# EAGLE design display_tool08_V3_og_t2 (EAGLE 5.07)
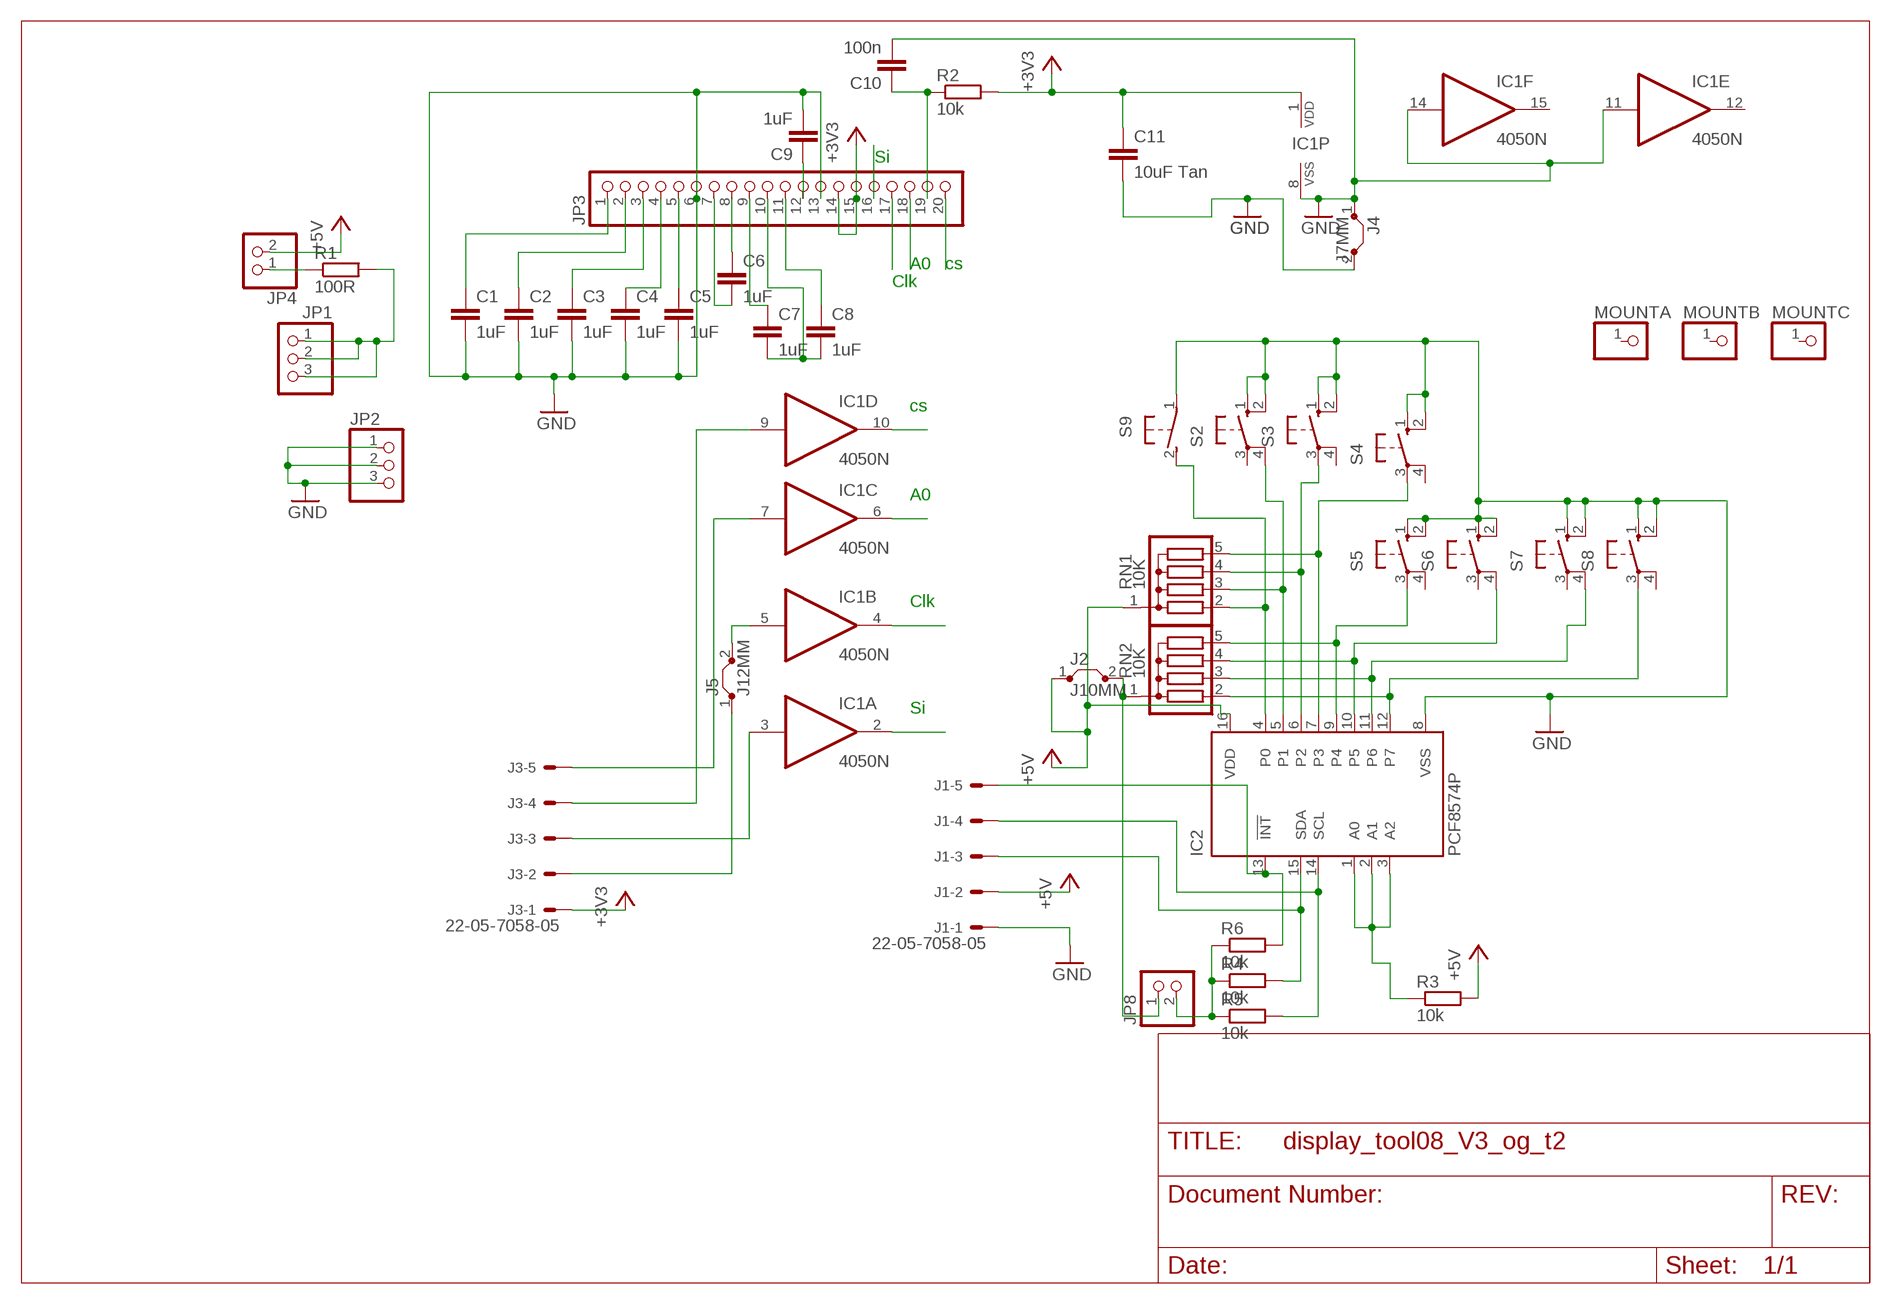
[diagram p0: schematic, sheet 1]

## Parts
C1  1uF  C-EU025-025X050  [C025-025X050]
C2  1uF  C-EU025-025X050  [C025-025X050]
C3  1uF  C-EU025-025X050  [C025-025X050]
C4  1uF  C-EU025-025X050  [C025-025X050]
C5  1uF  C-EU025-025X050  [C025-025X050]
C6  1uF  C-EU025-025X050  [C025-025X050]
C7  1uF  C-EU025-025X050  [C025-025X050]
C8  1uF  C-EU025-025X050  [C025-025X050]
C9  1uF  C-EU025-025X050  [C025-025X050]
C10  100n  C-EU025-025X050  [C025-025X050]
C11  10uF Tan  C-EU025-025X050  [C025-025X050]
IC1  4050N  [DIL16]
IC2  PCF8574P  [DIL16]
J1  22-05-7058-05  [7395-05]
J2  J10MM  [10]
J3  22-05-7058-05  [7395-05]
J4  J7MM  [07]
J5  J12MM  [12]
JP1  PINHD-1X3  [1X03]
JP2  PINHD-1X3  [1X03]
JP3  PINHD-1X20  [1X20]
JP4  PINHD-1X2  [1X02]
JP8  PINHD-1X2  [1X02]
MOUNTA  PINHD-1X1  [1X01]
MOUNTB  PINHD-1X1  [1X01]
MOUNTC  PINHD-1X1  [1X01]
R1  100R  R-EU_0309/12  [0309/12]
R2  10k  R-EU_0309/12  [0309/12]
R3  10k  R-EU_0207/7  [0207/7]
R4  10k  R-EU_0207/7  [0207/7]
R5  10k  R-EU_0207/7  [0207/7]
R6  10k  R-EU_0207/7  [0207/7]
RN1  10K  G04R  [SIL5]
RN2  10K  G04R  [SIL5]
S2  10-XX  [B3F-10XX]
S3  10-XX  [B3F-10XX]
S4  10-XX  [B3F-10XX]
S5  10-XX  [B3F-10XX]
S6  10-XX  [B3F-10XX]
S7  10-XX  [B3F-10XX]
S8  10-XX  [B3F-10XX]
S9  31-XX  [B3F-31XX]

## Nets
+3V3 [big]: C11.1 IC1.1(P:VDD) J3.1 JP3.14 JP3.15 R2.2
+5V [big]: IC2.16(VDD) J1.2 J2.1 JP4.2 R3.2 RN1.1
A0 [big]: IC1.6(C:O) JP3.18
CLK: IC1.4(B:O) JP3.17
CS: IC1.10(D:O) JP3.20
GND: C1.2 C2.2 C3.2 C4.2 C5.2 C9.2 C10.2 C11.2 IC1.8(P:VSS) IC1.11(E:I) IC1.14(F:I) IC2.8(VSS) J1.1 J4.1 J4.2 JP2.1 JP2.2 JP2.3 JP3.6 JP3.13 S2.1(S) S2.2(S1) S3.1(S) S3.2(S1) S4.1(S) S4.2(S1) S5.1(S) S5.2(S1) S6.1(S) S6.2(S1) S7.1(S) S7.2(S1) S8.1(S) S8.2(S1) S9.1(P)
N$1 [big]: JP4.1 R1.1
N$2 [big]: JP1.1 JP1.2 JP1.3 R1.2
N$3 [big]: IC2.7(P3) RN1.5 S4.3(P)
N$4 [big]: IC2.12(P7) RN2.2 S8.3(P)
N$5 [big]: C1.1 JP3.1
N$6 [big]: C2.1 JP3.2
N$7 [big]: C3.1 JP3.3
N$8 [big]: C4.1 JP3.4
N$9 [big]: C5.1 JP3.5
N$10 [big]: IC2.6(P2) RN1.4 S3.3(P)
N$11 [big]: IC2.11(P6) RN2.3 S7.4(P1)
N$12 [big]: C6.2 JP3.7
N$13 [big]: C6.1 JP3.8
N$14 [big]: C7.2 C8.2 JP3.10
N$15 [big]: IC2.5(P1) RN1.3 S2.4(P1)
N$16 [big]: C7.1 JP3.9
N$17 [big]: C8.1 JP3.11
N$18 [big]: C9.1 JP3.12
N$19 [big]: C10.1 JP3.19 R2.1
N$20 [big]: IC2.10(P5) RN2.4 S6.4(P1)
N$21 [big]: IC2.4(P0) RN1.2 S9.2(S)
N$22 [big]: IC2.9(P4) RN2.5 S5.3(P)
N$25 [mid]: IC1.3(A:I) J3.3
N$26 [big]: J3.2 J5.1
N$27 [mid]: IC1.7(C:I) J3.5
N$28: IC1.9(D:I) J3.4
N$29 [big]: IC1.5(B:I) J5.2
N$30 [big]: IC2.13(!INT) J1.5 R6.2
N$31: IC2.1(A0) IC2.2(A1) IC2.3(A2) R3.1
N$34 [big]: J2.2 JP8.1 RN2.1
N$35 [big]: JP8.2 R4.1 R5.1 R6.1
SCL [big]: IC2.14(SCL) J1.4 R5.2
SDA [big]: IC2.15(SDA) J1.3 R4.2
SI: IC1.2(A:O) JP3.16
Unconnected: IC1.12(E:O) IC1.15(F:O) MOUNTA.1 MOUNTB.1 MOUNTC.1 S2.3(P) S3.4(P1) S4.4(P1) S5.4(P1) S6.3(P) S7.3(P) S8.4(P1)

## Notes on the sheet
- Si
- A0 | cs
- Clk
- cs
- A0
- Clk
- Si

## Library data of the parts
C1-C11 = rcl:C-EU: CAPACITOR, European symbol
IC1 = 40xx:4050: Hex non-inverting BUFFER
IC2 = micro-philips:PCF8574: I2C-Bus Remote 8-bit I/O expander http://www.semiconductors.philips.com/acrobat_download/datasheets/PCF8574_4.pdf
J1 J3 = con-molex:22-?-05: CONNECTOR wire to board 2.54 mm (.1 inch) pitch header
J2 J4 J5 = jumper:J: Bridge
JP1 JP2 = pinhead:PINHD-1X3: PIN HEADER
JP3 = pinhead:PINHD-1X20: PIN HEADER
JP4 JP8 = pinhead:PINHD-1X2: PIN HEADER
MOUNTA MOUNTB MOUNTC = pinhead:PINHD-1X1: PIN HEADER
R1-R6 = rcl:R-EU_: RESISTOR, European symbol
RN1 RN2 = resistor-sil:G04R: SIL RESISTOR
S2-S8 = switch-omron:10-XX: OMRON SWITCH
S9 = switch-omron:31-XX: OMRON SWITCH

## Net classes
0 default: width 1.016 mm, drill 1.016 mm, clearance 0.762 mm
1 signal: width 0.813 mm, drill 1.016 mm, clearance 0.762 mm to class 0, clearance 0.762 mm
2 big: width 1.27 mm, clearance 0.762 mm to class 0, clearance 0.762 mm to class 1, clearance 0.762 mm
3 mid: width 1.016 mm, drill 1.016 mm, clearance 0.508 mm to class 0, clearance 0.508 mm to class 1, clearance 0.508 mm to class 2, clearance 0.508 mm

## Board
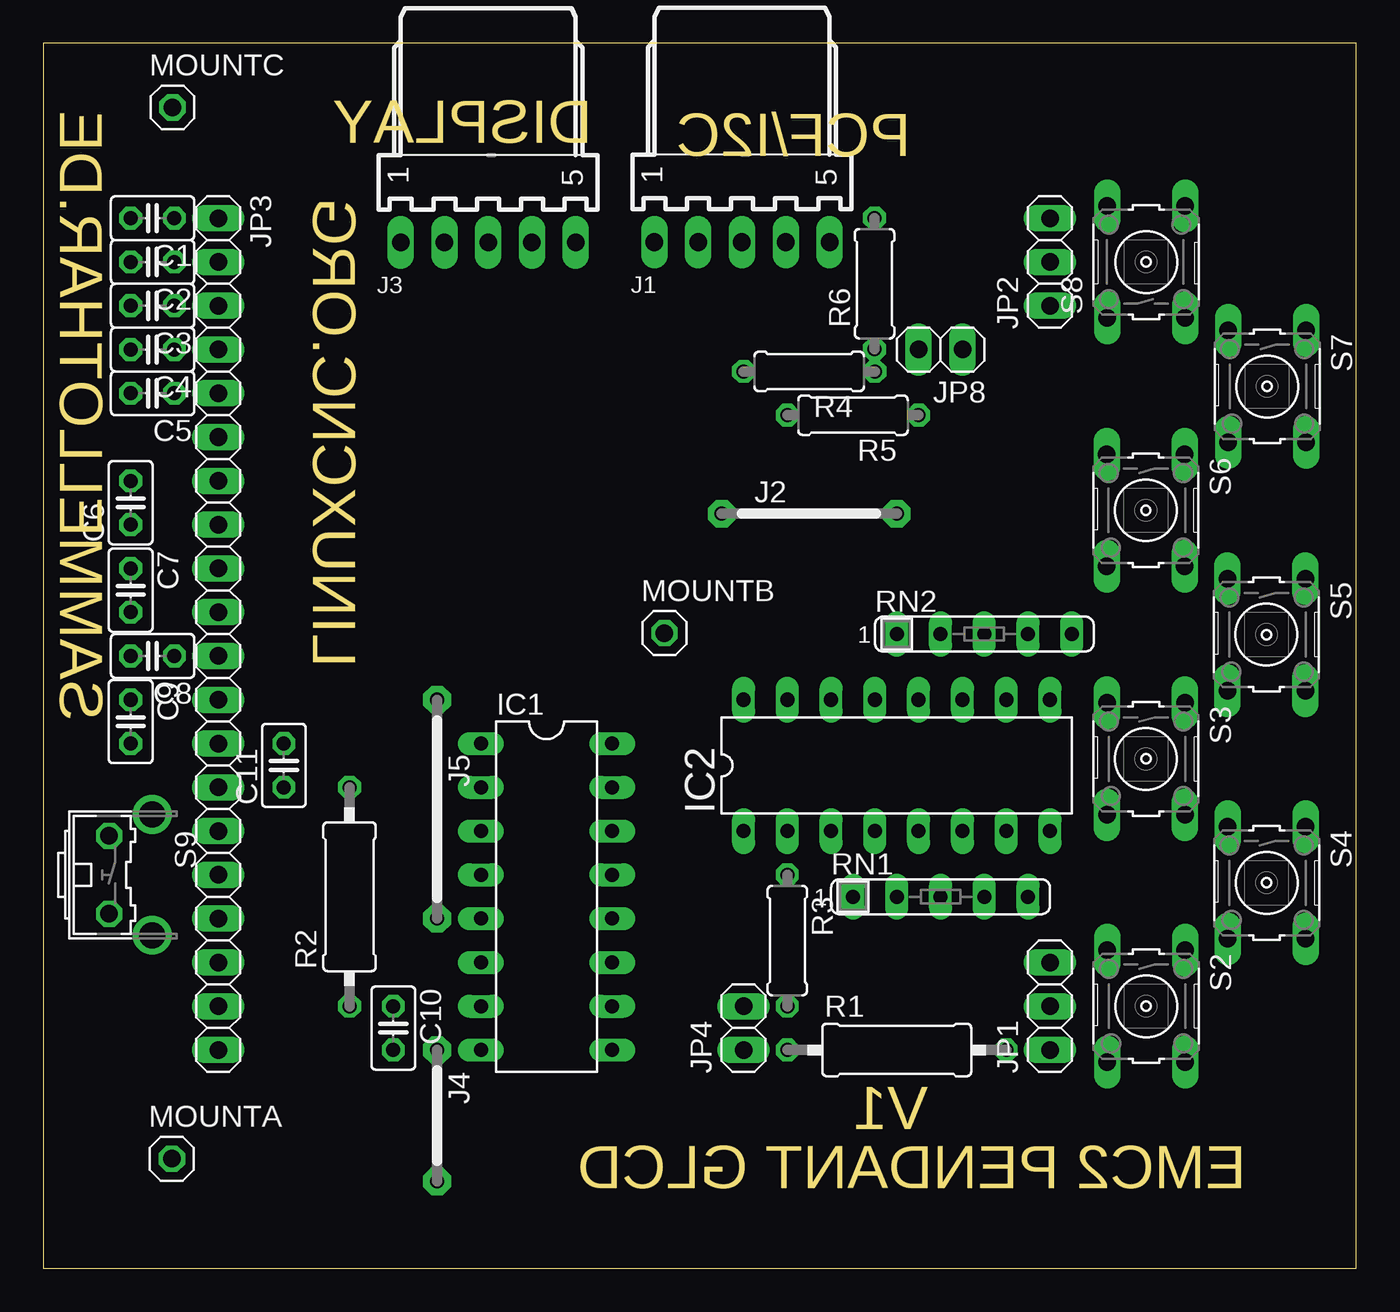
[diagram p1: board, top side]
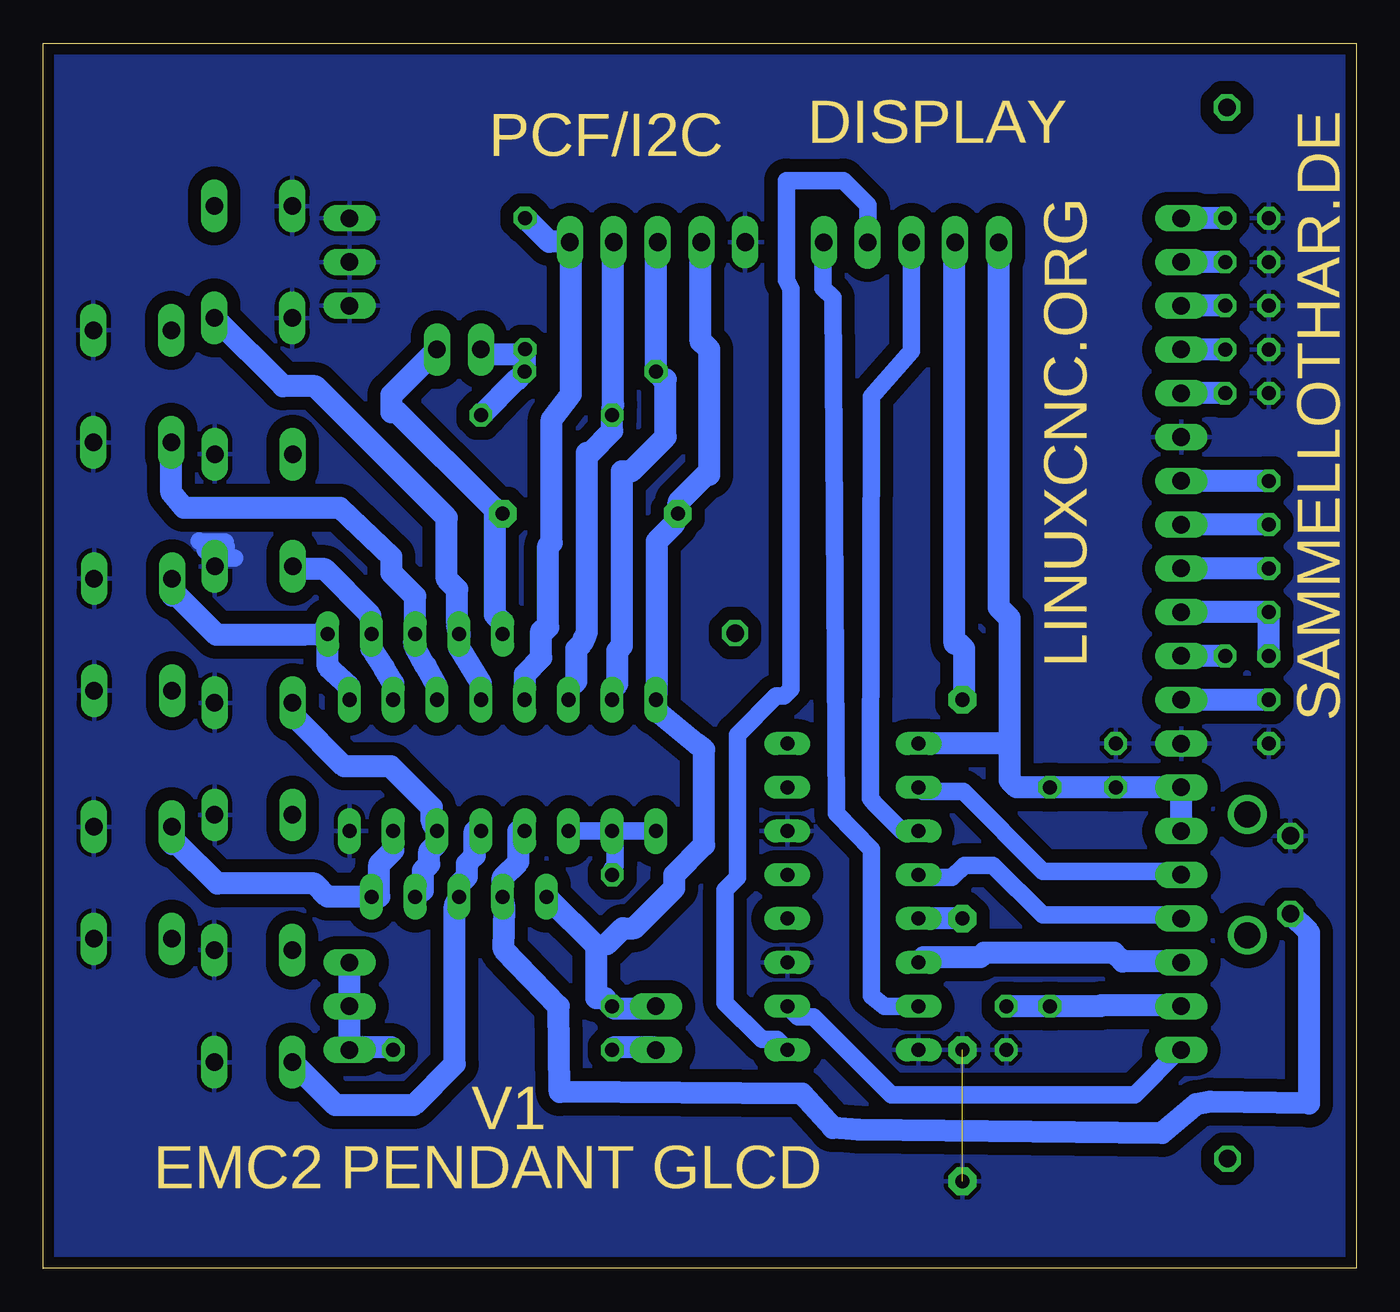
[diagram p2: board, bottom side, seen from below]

Size 76.2 x 71.12 mm. Coordinates in mm from the lower left corner, seen from the top.
Outline: 76.19,0.03 0,0.03 0,71.12 76.2,71.12 76.2,0
Copper layers (1*16): Top 0.035mm / dielectric 1.5mm / Bottom 0.035mm
Design rules "default *": minimum track width 10mil, minimum drill 24mil, track to track 8mil, track to pad 8mil, pad to pad 8mil, via to via 8mil, smd to smd 8mil, copper to edge 25mil, drill to drill 8mil, minimum pad ring 10mil, minimum via ring 8mil, stop-mask expansion 4mil, vias tented up to drill 0mil, thermal gap 10mil

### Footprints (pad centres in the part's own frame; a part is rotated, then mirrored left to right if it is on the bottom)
C025-025X050 = drill 0.813 octagon: 1 -1.27,0; 2 1.27,0
DIL16 = drill 0.813 long: 1 -8.89,-3.81; 2 -6.35,-3.81; 3 -3.81,-3.81; 4 -1.27,-3.81; 5 1.27,-3.81; 6 3.81,-3.81; 7 6.35,-3.81; 8 8.89,-3.81; 9 8.89,3.81; 10 6.35,3.81; 11 3.81,3.81; 12 1.27,3.81; 13 -1.27,3.81; 14 -3.81,3.81; 15 -6.35,3.81; 16 -8.89,3.81
7395-05 = drill 1.016 long: 1 5.08,0; 2 2.54,0; 3 0,0; 4 -2.54,0; 5 -5.08,0
10 = drill 0.813 pad 1.6 octagon: 1 -5.08,0; 2 5.08,0
07 = drill 0.813 pad 1.6 octagon: 1 -3.81,0; 2 3.81,0
12 = drill 0.813 pad 1.6 octagon: 1 -6.35,0; 2 6.35,0
1X03 = drill 1.016 long: 1 -2.54,0; 2 0,0; 3 2.54,0
1X20 = drill 1.016 long: 1 -24.13,0; 2 -21.59,0; 3 -19.05,0; 4 -16.51,0; 5 -13.97,0; 6 -11.43,0; 7 -8.89,0; 8 -6.35,0; 9 -3.81,0; 10 -1.27,0; 11 1.27,0; 12 3.81,0; 13 6.35,0; 14 8.89,0; 15 11.43,0; 16 13.97,0; 17 16.51,0; 18 19.05,0; 19 21.59,0; 20 24.13,0
1X02 = drill 1.016 long: 1 -1.27,0; 2 1.27,0
1X01 = drill 1.016 octagon: 1 0,0
0309/12 = drill 0.813 octagon: 1 -6.35,0; 2 6.35,0
0207/7 = drill 0.813 octagon: 1 -3.81,0; 2 3.81,0
SIL5 = drill 0.813 long: 1 -5.08,0; 2 -2.54,0; 3 0,0; 4 2.54,0; 5 5.08,0
B3F-10XX = drill 1.016 long: 1 -3.251,2.261; 2 3.251,2.261; 3 -3.251,-2.261; 4 3.251,-2.261
B3F-31XX = drill 1.016 octagon: 1 -2.261,-1.245; 2 2.261,-1.245 | drill 1.499 pad 2.159 round: 3 -3.505,1.245; 4 3.505,1.245

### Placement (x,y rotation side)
C1  6.35,60.96 180 top
C2  6.35,58.42 180 top
C3  6.35,55.88 180 top
C4  6.35,53.34 180 top
C5  6.35,50.8 180 top
C6  5.08,44.45 90 top
C7  5.08,39.37 270 top
C8  6.35,35.56 180 top
C9  5.08,31.75 270 top
C10  20.32,13.97 270 top
C11  13.97,29.21 90 top
IC1  29.21,21.59 270 top
IC2  49.53,29.21 0 top
J1  40.55,59.57 180 top
J2  44.45,43.81 0 top
J3  25.82,59.55 180 top
J4  22.86,8.89 270 top
J5  22.86,26.67 270 top
JP1  58.42,15.24 90 top
JP2  58.42,58.42 90 top
JP3  10.16,36.83 270 top
JP4  40.64,13.97 90 top
JP8  52.07,53.34 180 top
MOUNTA  7.47,6.39 0 top
MOUNTB  36.05,36.89 0 top
MOUNTC  7.51,67.39 0 top
R1  49.53,12.7 0 top
R2  17.78,21.59 90 top
R3  43.18,19.05 270 top
R4  44.45,52.07 180 top
R5  46.99,49.53 180 top
R6  48.24,57.16 90 top
RN1  52.07,21.59 0 top
RN2  54.61,36.83 0 top
S2  64,15.24 270 top
S3  63.99,29.59 270 top
S4  70.99,22.4 270 top
S5  70.98,36.8 270 top
S6  63.98,44.01 270 top
S7  71.02,51.2 270 top
S8  64,58.42 90 top
S9  5.08,22.86 270 top

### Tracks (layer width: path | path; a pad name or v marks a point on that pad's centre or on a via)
+3V3
  Bottom 1.27: JP3.15 JP3.14 C11.1 R2.2 19.71,27.94 20.12,28.35 20.12,30.12 | J3.1 20.75,38.37 20.12,37.74 20.12,30.12 | IC1.1 20.47,30.48 20.12,30.12
+5V
  Bottom 1.27: J1.2 38.05,59.54 38.05,53.8 38,53.8 37.54,53.34 37.54,46.08 37.74,46.08 39.32,44.5 39.32,43.84 39.37,43.84 J2.1 39.57,43.23 40.59,42.22 40.59,33.48 IC2.16 40.64,32.41 38.3,30.48 37.85,30.12 37.85,24.59 39.57,22.86 39.57,22.1 41.91,19.76 42.57,19.76 43.48,18.85 44.09,18.69 | JP4.2 40.79,15.09 43.03,15.09 R3.2 43.59,15.7 44.09,15.7 44.09,18.69 | 44.09,18.69 RN1.1
A0
  Bottom 1.27: IC1.6 25.09,18.09 21.84,18.09 21.59,18.34 14.07,18.34 13.56,17.83 10.21,17.83 JP3.18
CLK
  Bottom 1.016: IC1.4 25.25,22.71 23.47,22.71 22.76,23.42 21.08,23.42 18.19,20.52 11.18,20.52 10.97,20.32 JP3.17
CS
  Bottom 1.016: IC1.10 32.41,14.63 31.5,14.63 26.98,10.11 12.85,10.11 10.26,12.7 JP3.20
GND  (1 unrouted)
  Bottom 1.016: 65.1,41.25 66.04,41.25 66.09,41.3 66.34,41.3 66.45,41.4 66.45,41.45 65.89,41.45 65.79,41.55 65.79,41.66 66.75,41.66 66.8,41.71 66.8,41.76 65.68,41.76 65.58,41.86 65.58,41.91 66.75,41.91 66.85,42.01 66.85,42.06 66.55,42.06 66.5,42.01 65.68,42.01 65.63,42.06 65.63,42.16 67.06,42.16 67.14,42.23
  pour Bottom (isolate 0.25): 0.25,0 76.15,0 76.15,71.07 0.15,71.07 0.15,-0.15
N$1
  Bottom 1.27: R1.1 43.03,12.85 40.79,12.85 JP4.1
N$2
  Bottom 1.27: R1.2 56.03,12.85 58.27,12.85 | 58.27,12.85 JP1.1 | 58.27,12.85 58.42,13.46 JP1.2 JP1.3
N$3
  Bottom 1.27: IC2.7 55.88,24.28 56.69,23.47 56.69,21.59 RN1.5 59.69,21.59 60.45,22.35 66.09,22.35 68.38,24.64 68.68,24.64 68.68,25.6 S4.3
N$4
  Bottom 1.27: IC2.12 50.8,33.98 52.07,36.07 52.07,37.03 52.02,36.78 RN2.2 52.17,37.44 52.17,39.42 52.78,40.03 52.78,43.59 60.4,51.21 62.28,51.21 66.24,55.17 S8.3
N$5
  Bottom 1.27: C1.1 JP3.1
N$6
  Bottom 1.27: C2.1 JP3.2
N$7
  Bottom 1.27: C3.1 JP3.3
N$8
  Bottom 1.27: C4.1 JP3.4
N$9
  Bottom 1.27: C5.1 JP3.5
N$10
  Bottom 1.27: RN1.4 54.56,21.59 54.2,21.95 54.15,21.95 54.15,23.11 53.8,23.47 53.8,24.23 53.34,24.69 IC2.6 53.65,25.96 53.65,26.77 56.03,29.16 58.73,29.16 61.52,31.95 61.72,31.95 61.72,32.82 S3.3
N$11
  Bottom 1.27: IC2.11 53.34,33.78 54,35 54,34.95 54.56,35.97 54.56,36.12 54.66,36.22 RN2.3 54.61,39.01 55.98,40.39 55.98,41.3 58.98,44.15 68.02,44.15 68.76,45.04 S7.4
N$12
  Bottom 1.27: C6.2 JP3.7
N$13
  Bottom 1.27: C6.1 JP3.8
N$14
  Bottom 1.27: C8.2 C7.2 JP3.10
N$15
  Bottom 1.27: IC2.5 51.16,25.4 51.16,23.98 51.61,23.52 51.61,22.76 52.07,22.3 RN1.3 52.32,21.03 52.32,11.89 54.71,9.5 59.23,9.5 61.72,11.99 S2.4
N$16
  Bottom 1.27: C7.1 JP3.9
N$17
  Bottom 1.27: C8.1 JP3.11
N$18
  Bottom 1.27: C9.1 JP3.12
N$19
  Bottom 1.27: C10.1 R2.1 14.83,15.24 14.78,15.29 10.21,15.29 JP3.19
N$20
  Bottom 1.27: IC2.10 55.88,33.98 56.44,34.9 57.15,35.97 RN2.4 57.2,37.9 57.3,38.05 59.84,40.59 61.52,40.59 61.67,40.74 S6.4
N$21
  Bottom 1.27: IC2.4 48.62,25.4 48.62,23.62 49.53,22.71 RN1.2 49.43,20.98 49.48,18.54 46.28,15.24 46.23,10.26 32.16,10.16 30.38,8.18 28.91,8.08 11.28,7.87 9.3,9.55 8.48,9.7 2.74,9.6 2.74,19.51 S9.2
N$22
  Bottom 1.27: IC2.9 58.42,33.78 59.69,34.95 59.69,36.73 59.74,36.78 RN2.5 61.06,36.78 66.14,36.78 68.43,39.06 68.68,39.06 68.68,40.03 S5.3
N$25
  Bottom 1.016: IC1.3 26.36,25.4 27.94,26.98 28.19,27.28 28.14,50.6 25.81,53.24 25.81,58.93 25.7,59.03 25.7,59.43 J3.3
N$26
  Bottom 1.27: J5.1 22.76,33.02 22.76,35.97 23.06,36.27 23.32,36.27 23.32,59.54 J3.2
N$27
  Bottom 1.016: IC1.7 27.38,15.24 28.14,15.85 28.14,24.33 30.18,26.42 30.38,56.34 30.94,56.9 30.94,59.52 J3.5
N$28
  Bottom 1.016: IC1.9 33.63,13.31 34.49,13.31 36.63,15.44 36.63,22 35.92,22.71 35.92,30.99 33.68,33.22 33.22,33.22 32.82,33.63 32.82,56.84 33.07,57.35 33.07,63.14 29.77,63.14 28.35,61.72 28.35,59.59 J3.4
N$29
  Bottom 1.27: J5.2 IC1.5
N$30
  Bottom 1.27: R6.2 48.21,60.96 46.84,59.59 45.67,59.59 J1.5 45.57,58.98 45.57,50.75 46.69,49.28 46.69,42.11 46.84,41.96 46.89,41.96 46.89,37.24 47.09,37.03 47.3,37.03 47.3,35.46 48.26,34.49 IC2.13
N$31
  Bottom 1.016: IC2.2 IC2.1 | R3.1 43.18,23.22 43.03,23.37 43.03,24.94 IC2.2 | IC2.2 IC2.3
N$34
  Bottom 1.27: RN2.1 49.53,37.54 49.58,37.54 49.99,37.95 49.99,43.69 49.73,43.69 49.63,43.79 49.53,43.79 J2.2 50.19,44.25 55.63,49.68 55.98,49.68 55.98,50.7 JP8.1
N$35
  Bottom 1.27: 48.26,53.03 R4.1 48.67,51.61 48.72,51.61 R5.1 | 48.26,53.03 48.26,53.34 R6.1 | JP8.2 50.49,53.03 48.26,53.03
SCL
  Bottom 1.27: IC2.14 45.72,33.68 45.67,33.68 45.26,34.09 45.26,35.97 44.91,36.32 44.76,36.68 44.65,36.93 44.65,47.35 44.45,47.35 43.18,48.62 R5.2 43.13,50.14 43.13,59.54 J1.4
SDA
  Bottom 1.27: J1.3 40.59,59.54 40.64,59.54 R4.2 40.23,51.61 40.08,51.61 40.08,48.26 42.06,46.28 42.62,46.28 42.62,36.12 42.88,35.87 42.88,33.93 43.13,33.68 43.18,33.68 IC2.15
SI
  Bottom 1.016: IC1.2 25.15,27.69 22.81,27.69 18.19,23.06 11.18,23.06 10.97,22.86 JP3.16

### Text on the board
Milling: DISPLAY | SAMMELLOTHAR.DE | PCF/I2C | LINUXCNC.ORG | V1 | EMC2 PENDANT GLCD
